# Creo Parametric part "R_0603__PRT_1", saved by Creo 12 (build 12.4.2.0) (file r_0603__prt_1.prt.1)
Units: Custom; MM, KILOGRAM, SECS

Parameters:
  PTC_WM_ITERATION = "0"
  PTC_WM_VERSION = "-.0"
  PTC_WM_LIFECYCLE_STATE = "In Work"
  PTC_WM_LIFECYCLE = "MO_CADDocument"
  PTC_WM_CREATED_BY = "Maximilian Roepper (Z0017RMS: MO)"
  PTC_WM_CREATED_ON = "18-Sep-26 11:36:42 AM"
  PTC_WM_MODIFIED_BY = "Maximilian Roepper (Z0017RMS: MO)"
  PTC_WM_MODIFIED_ON = "18-Sep-26 11:36:46 AM"
  PDMLINKNUMBER = "PDM000071455072"
  PTC_WM_NAME = "r_0603__prt_1.prt"
  PTC_WM_NUMBER = "PDM000071455072"

Other parameters: WEIGHT, WEIGHT_FACTOR, WEIGHT_ADD, _MASS_TEMP, _DIFF_TEMP, MC_ERRORS, SUPPLIER

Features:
  1. coordinate system
  2. datum plane "PRT_YZ"
  3. datum plane "PRT_XY"
  4. datum plane "PRT_XZ"
  5. coordinate system
  6. datum axis
  7. datum axis
  8. datum axis
  9. coordinate system
  10. imported feature
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
Other named items: PRT, SIEMENS_MO, DRW_VIEW_ORG, PRT_X, PRT_Y, PRT_Z, CS0, ROUGH_GROB

Layers: 00_STD_CSYS-KSYS, 01_STD_PLANES-EBENEN, 02_STD_AXES-ACHSEN, 03_STD_CSYS-KSYS, 24_IMPORT_FEAT-IMPORT_KE

Surfaces: 18 plane, 8 cylinder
